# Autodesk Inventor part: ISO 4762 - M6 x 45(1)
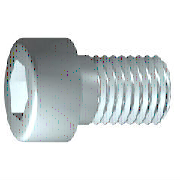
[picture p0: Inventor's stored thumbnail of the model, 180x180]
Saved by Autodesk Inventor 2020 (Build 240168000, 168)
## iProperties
Created: 2019-01
Part Number: ISO 4762 - M6 x 45(1)
Material: Nerezová ocel 440C
Description: Šroub s válcovou hlavou s vnitřním šestihranem
Document SubType Name: Modeling
Standard: ISO 4762
Designer: doma
Standard Revision: Fourth edition 2004-03-01
Standards Organization: ISO
Language: cs-CZ
Size Designation: M6 x 45
Categories: <MemberInstance><Categories><Category DisplayName="Spojovací materiál" InternalName="e4da775c-781d-43d5-af7c-5136215cf5a6" Mnemonic="FSTN"><Category DisplayName
Density: 7.75 g/cm^3
Appearance: Pololeštěná
IsCustomPart: 0
Author: doma
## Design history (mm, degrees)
sketch "Náčrt1"
  geometry: L1 (-1.333, 0)-(45, 0); L2 (45, 0)-(45, 3); L3 (45, 3)-(21, 3); L4 (21, 3)-(20.386, 3); L5 (20.386, 3)-(0, 3); L6 (0, 3)-(0, 5); L7 (0, 5)-(-6, 5); L8 (-6, 5)-(-6, 2.887); L9 (-6, 2.887)-(-3, 2.887); L10 (-3, 2.887)-(-1.333, 0); L11 (-16.2, 0)-(55.2, 0) reference; L12 (0, -1)-(0, 6) reference; L13 (21, 3)-(0, 3)
  constraints: 22 end point, 6 parallel, 2 collinear, 2 perpendicular, 1 horizontal, 1 point on line
  dimensions: "d1" = 24 distance from line of L3.end L2 (= GEL); "d2" = 0.61355 distance of L4.end L3.end (computed from GAL); "d3" = 6 distance between parallel lines of L8 L6 (= KOH); "d4" = 3 distance of L8.end L9.end (= INTI); "d5" = 60 deg angle of L10 L1; "d6" = 6 diameter of L3 L1 (= GD); "d7" = 6 diameter of L5 L1 (= BDM); "d8" = 5.7735 diameter of L9 L1 (= 1.1547 x SW); "d9" = 10 diameter of L7 L1 (= KOD); "d26" = 45 distance between parallel lines of L12 L2 (= NLG)
revolve "Těleso" sketch "Náčrt1" stored, may be unused: angle "d10" = 90 deg
sketch "Náčrt2"
  geometry: L1 (0, -7)-(0, 7) reference; L2 (-7, 0)-(7, 0) reference; L3 (2.887, 0)-(1.443, -2.5); L4 (1.443, -2.5)-(-1.443, -2.5); L5 (-1.443, -2.5)-(-2.887, 0); L6 (-2.887, 0)-(-1.443, 2.5); L7 (-1.443, 2.5)-(1.443, 2.5); L8 (1.443, 2.5)-(2.887, 0); 2 further points
  constraints: 12 end point, 1 coincident, 1 horizontal alignment, 1 point on line, 12 other
extrude "Drážka" join sketch "Náčrt2" stored distance "d11" = 10; taper "d12" = 0 deg
workplane "Work Plane1"
fillet "Fillet2" dims "d30" = 0.1 (= R)
body "Solid1"
fillet "Zaoblení1" dims "d17" = 0.6 (= RR)
feature "Závit" dims "d13" = 24 (= GEL), "d14" = 0
chamfer "Zkosení1" distance "d15" = 0.61345 (= -0.5 x SPD + 0.5 x GD); stored, may be unused: second distance "d16" = 0.61345 (= GUL), angle "d27" = 45 deg
other parameters: "GD" = 6 [user parameter; used in 2 equation terms], "NLG" = 45 [user parameter; used in 1 equation term], "GEL" = 24 [user parameter; used in 2 equation terms], "KOD" = 10 [user parameter; used in 1 equation term], "KOH" = 6 [user parameter; used in 1 equation term], "INTI" = 3 [user parameter; used in 1 equation term], "GAL" = 0.61345 (= 0.61345 x PTC) [user parameter; used in 1 equation term], "GUL" = 0.61345 (= 0.61345 x PTC) [user parameter; used in 1 equation term], "BDM" = 6 (= NND) [user parameter; used in 1 equation term], "SW" = 5 [user parameter; used in 2 equation terms], "RR" = 0.6 [user parameter; used in 1 equation term], "SPD" = 4.7731 (= NND - 1.2269 x PTC) [user parameter; used in 1 equation term], "d19" = 0, "d28" = 0, "d29" = 0, "R" = 0.1 [user parameter; used in 1 equation term], "TOA" = 30 deg [user parameter], "GD1" = 4.7731 (= THREADDIA - 1.2269 x PTC) [user parameter], "THREADDIA" = 6 [user parameter; used in 1 equation term], "FAWI" = 45 deg [user parameter], "PTC" = 1 [user parameter; used in 5 equation terms], "NND" = 6 [user parameter; used in 2 equation terms], "E0" = 5.775 (= 1.155 x SW) [user parameter]
